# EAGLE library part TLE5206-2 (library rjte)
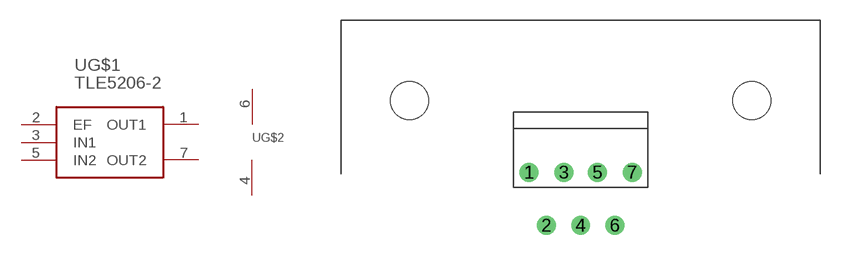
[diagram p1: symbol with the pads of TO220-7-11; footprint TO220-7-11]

Designator prefix U; gates G$1=TLE5206-2 G$2=VS-GND

## TLE5206-2TLE5206-2  [TO220-7-11]
1  G$1:OUT1  out
2  G$1:EF
3  G$1:IN1  in
4  G$2:GND  pwr
5  G$1:IN2  in
6  G$2:VS  pwr
7  G$1:OUT2  out

## Footprint TO220-7-11 (pad centres in mm)
drill 0.9 round: 1 -3.82,3.94; 2 -2.54,0; 3 -1.24,3.94; 4 0,0; 5 1.24,3.94; 6 2.54,0; 7 3.82,3.94
hole 2.8 at -12.7,9.271
hole 2.8 at 12.7,9.271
